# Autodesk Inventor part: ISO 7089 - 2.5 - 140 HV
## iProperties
Created: 2008-01
Part Number: ISO 7089 - 2.5 - 140 HV
Material: Stainless Steel
Description: Plain washers - Normal series - Product grade A
Document SubType Name: Modeling
Standard: ISO 7089
Designer: latalom
Standard Revision: Second edition 2000-06-01
Standards Organization: ISO
Language: en-US
Size Designation: 2.5 - 140 HV
Categories: <MemberInstance><Categories><Category DisplayName="Fasteners" InternalName="e4da775c-781d-43d5-af7c-5136215cf5a6" Mnemonic="FSTN"><Category DisplayName="Washers
Density: 8.08 g/cm^3
IsCustomPart: 0
Author: latalom
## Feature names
1. Body [Extrusion]
